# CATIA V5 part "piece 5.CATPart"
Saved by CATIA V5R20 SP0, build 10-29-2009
Part number: piece 5
Bounding box of the stored display mesh (mm): x -233.779 to 126.221, y -5 to 5, z 0 to 2
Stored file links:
  G:\Khaled_CFAO_2011\SIL\SIL_GR1\blaboucarri\Khaled\CAD_CATIA\piece 5.CATPart
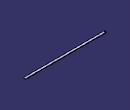
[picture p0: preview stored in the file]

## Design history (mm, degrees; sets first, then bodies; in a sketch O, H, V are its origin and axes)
Parameters
  `longueur piece 5` = 360 mm
  largeur = 10 mm
  epaisseur = 2 mm
  `rayon trou` = 1.5 mm
  `trou distance bord` = 2 mm
  `trou distance coté` = 5 mm
Body1 (main body)
  Sketch1 on xy-plane, origin (0, 0, 0), H (1, 0, 0), V (0, 1, 0)
    line L1 (-230.081, 5) -> (122.6733, 5)
    line L2 (126.2206, 1.4527) -> (126.2206, -1.2627)
    line L3 (122.4833, -5) -> (-230.4336, -5)
    line L4 (-233.7794, -1.6542) -> (-233.7794, 1.3016)
    point P1 (126.2206, 5)
    point P2 (126.2206, -5)
    point P3 (-233.7794, -5)
    circle A1 centre (-230.2794, 0) radius 1.5
    point P4 (-230.2794, 0)
    arc A2 centre (-230.081, 1.3016) radius 3.6984 from (-230.081, 5) to (-233.7794, 1.3016) ccw
    arc A3 centre (-230.4336, -1.6542) radius 3.3458 from (-230.4336, -5) to (-233.7794, -1.6542) cw
    arc A4 centre (122.6733, 1.4527) radius 3.5473 from (122.6733, 5) to (126.2206, 1.4527) cw
    arc A5 centre (122.4833, -1.2627) radius 3.7373 from (126.2206, -1.2627) to (122.4833, -5) cw
    radius A1 = 1.5 {= `rayon trou`}
    distance P4 L4 = 3.5 {= `trou distance bord` +`rayon trou`}
    distance P4 L3 = 5 {= `trou distance coté`}
    radius A2 = 3.6984
    distance P2 P3 = 360 {= `longueur piece 5`}
    radius A3 = 3.3458
    distance P1 P2 = 10 {= largeur}
    radius A4 = 3.5473
    radius A5 = 3.7373
    horizontal: L1 H, L3 H
    vertical: L2 V, L4 V
    coincidence: P4 H, L3 P3, L4 P3, L1 P1, L2 P1, L2 P2, L3 P2
    tangency: A2 L1, A2 L4, A3 L3, A3 L4, A4 L1, A4 L2, A5 L2, A5 L3
  Pad1: profile Sketch1, direction (0, 0, 1), length 2 {= epaisseur}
